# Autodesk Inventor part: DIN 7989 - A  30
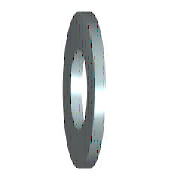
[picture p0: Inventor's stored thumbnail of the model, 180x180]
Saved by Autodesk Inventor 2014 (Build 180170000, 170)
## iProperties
Created: 2013-02
Part Number: DIN 7989 - A  30
Material: Steel, Mild
Description: Washer
Document SubType Name: Modeling
Standard: DIN 7989
Designer: Thom Tremblay
Standards Organization: DIN
Language: en-US
Size Designation: A  30
Categories: <MemberInstance><Categories><Category DisplayName="Fasteners" InternalName="e4da775c-781d-43d5-af7c-5136215cf5a6" Mnemonic="FSTN"><Category DisplayName="Washers
Density: 1 g/cm^3
Appearance: Steel
IsCustomPart: 0
Author: Thom Tremblay
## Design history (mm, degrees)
sketch "Sketch"
  geometry: C1 r 25 at (0, 0); C2 r 15 at (0, 0); 1 further point
  constraints: 2 centre point, 2 coincident
  dimensions: "d0" = 30 diameter of C2 (= SD1); "d1" = 50 diameter of C1 (= SD2)
extrude "Body" new body sketch "Sketch" distance "d2" = 8 (= SD); taper "d3" = 0 deg
workaxis "Work Axis1"
workplane "Work Plane1"
body "Solid1"
other parameters: "SD1" = 30 [user parameter; used in 1 equation term], "SD2" = 50 [user parameter; used in 1 equation term], "SD" = 8 [user parameter; used in 1 equation term], "d4" = 0, "d5" = 0, "d6" = 0, "d7" = 0, "NND" = 27 [user parameter]
